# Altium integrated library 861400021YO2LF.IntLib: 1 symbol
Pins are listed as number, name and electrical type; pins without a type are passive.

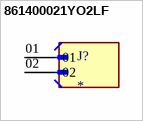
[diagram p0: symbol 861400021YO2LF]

## 861400021YO2LF
designator J?
Board to Board connector, Unshrouded Header, Through Hole, Single Row, 2 Position, Vertical.; MF: Amphenol ICC (FCI); MP: 861400021YO2LF
footprint AMPHENOL_861400021YO2LF
pins: 01, 02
